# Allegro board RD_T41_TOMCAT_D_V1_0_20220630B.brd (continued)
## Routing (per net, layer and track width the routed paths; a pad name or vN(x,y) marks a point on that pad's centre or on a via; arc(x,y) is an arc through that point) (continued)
DVP_D7: length 16.4
  TOP w0.102: U6.H3 32.65,28.36
  TOP w0.104: v1(23.03,35.33) 23.03,34.8 23.92,33.91 28.04,33.91 28.34,33.6 30.1,33.6 32.3,31.39 32.3,30.28 32.46,30.12 32.46,29.11 32.67,28.9 32.67,28.38 32.65,28.36
  BOTTOM w0.104: v1(23.03,35.33) 23.03,35.46 22.27,36.22 J3.19
DVP_D8: length 14.6
  TOP w0.102: 33,29.46 U6.G1
  TOP w0.104: v1(23.62,35.56) 23.92,35.26 23.92,34.87 24.38,34.42 28.32,34.42 28.6,34.14 30.27,34.14 32.81,31.6 32.81,30.56 32.97,30.4 32.97,29.49 33,29.46
  BOTTOM w0.104: J3.21 23.27,35.91 v1(23.62,35.56)
DVP_D9: length 14.7
  TOP w0.102: 32.97,28.74 U6.G2
  TOP w0.104: v1(23.49,34.92) 23.49,34.9 24.23,34.16 28.22,34.16 28.49,33.88 30.17,33.88 32.56,31.5 32.56,30.38 32.71,30.23 32.71,29.64 32.69,29.62 32.69,29.23 32.97,28.96 32.97,28.74
  BOTTOM w0.104: v1(23.49,34.92) 23.57,34.92 23.77,34.72 J3.22
DVP_D10: length 15.8
  TOP w0.102: U6.G3 33.32,28.38 33.32,29.49 33.22,29.59 33.22,30.51 33.07,30.66 33.07,31.7 30.37,34.39 28.7,34.39 28.67,34.42
  TOP w0.104: v1(24.28,35.64) 24.18,35.53 24.18,34.98 24.48,34.67 28.42,34.67 28.67,34.42
  BOTTOM w0.104: J3.23 24.27,36.23 24.28,36.22 v1(24.28,35.64)
DVP_D11: length 14.7
  TOP w0.102: 30.45,34.65 33.3,31.8 33.3,30.78 33.52,30.56 33.52,28.83 U6.F2
  TOP w0.104: v1(24.56,35.15) 24.76,34.95 28.49,34.95 28.8,34.65 30.45,34.65
  BOTTOM w0.104: J3.24 24.77,34.94 v1(24.56,35.15)
DVP_HSYNC: length 19.9
  TOP w0.102: U6.J2 31.67,28.73 31.67,28.93 31.34,29.26 31.34,30.94 30.37,31.9 v1(29.87,31.9)
  L3_PWR w0.102: v1(16.84,34.7) 17.12,34.42 18.72,34.42 19.38,33.76 28.88,33.76 30.04,32.59 30.04,32.08 v1(29.87,31.9)
  BOTTOM w0.102: J3.8 16.77,34.63 v1(16.84,34.7)
DVP_PCLK: length 14.5
  TOP w0.102: v1(28.29,35.59) 28.29,35.51 28.9,34.9 30.53,34.9 33.55,31.88 33.55,30.89 33.78,30.66 33.78,29.01 33.95,28.84 33.95,28.54 33.65,28.24 U6.F3
  BOTTOM w0.102: v1(28.29,35.59) 28.29,35.38 28.11,35.2 26.78,35.2 25.77,34.19 J3.26
DVP_PWDN: length 12.1
  TOP w0.102: v1(33.12,32.87) 33.14,32.84 33.14,32.61 33.78,31.98 33.78,30.99 34.01,30.76 34.01,29.64 33.98,29.62 33.98,29.21 34.01,29.18 34.01,29.13 34.3,28.85 U6.E2
  L3_PWR w0.102: v1(28.83,35.51) 29.18,35.51 31.59,33.1 32.89,33.1 v1(33.12,32.87)
  BOTTOM w0.102: J3.30 27.77,34.4 28.83,35.46 v1(28.83,35.51)
DVP_RST: length 12.3
  TOP w0.102: U6.E3 34.64,28.4 34.64,29.62 34.87,29.84 34.87,31.67 34.57,31.98 34.57,32.11 34.36,32.31 33.96,32.31 v1(33.63,32.64)
  L3_PWR w0.102: v1(29.76,35.66) 29.76,35.36 31.77,33.35 33.27,33.35 33.68,32.94 33.68,32.69 v1(33.63,32.64)
  BOTTOM w0.102: J3.33 29.27,36.21 29.76,35.71 v1(29.76,35.66)
DVP_VSYNC: length 20.1
  TOP w0.102: v1(30.27,31.5) 30.27,31.47 31.11,30.63 31.11,29.08 31.37,28.83 31.37,28.39 U6.J3
  L3_PWR w0.102: v1(18.56,35) 18.56,34.92 19.5,33.99 28.98,33.99 30.27,32.69 v1(30.27,31.5)
  BOTTOM w0.102: v1(18.56,35) 17.27,36.3 J3.9
EN_DLDO: length 6
  TOP w0.102: U6.U15 26.17,20.26 24.79,18.87 23.49,18.87 22.98,18.36 22.98,17.73 v1(22.68,17.42)
  BOTTOM w0.102: v1(22.68,17.42) 23.1,17.01 R27.2
EXCLKI: length 4.9
  TOP w0.102: C80.2 36.94,32.53 Y1.1 37.05,32.36 37.05,30.82 R23.2 35.6,29.36 U6.C1
EXCLKO: length 2.8
  TOP w0.102: U6.D2 35.25,29.01 35.25,29.49 35.57,29.81 R23.1 R24.2
GMAC_MDCK: length 13.9
  TOP w0.102: U8.22 15.58,20.57 16.43,21.42 16.43,21.87 17.6,23.04 26.23,23.04 26.36,23.16 27.45,23.16 U6.R10
GMAC_MDIO: length 13.7
  TOP w0.102: U6.T10 27.01,23.37 26.26,23.37 26.16,23.27 17.38,23.27 R37.2 15.08,20.96 U8.23
GMAC_PHY_CLK: length 16.5
  TOP w0.102: U8.31 v1(13.25,16.68) ; v1(15.19,23.39) 15.34,23.55 22.82,23.55 R66.1
  L3_PWR w0.102: v1(13.25,16.68) 13.94,17.37 13.94,19.46 15.44,20.95 15.44,23.14 v1(15.19,23.39)
GMAC_RST_N: length 46.5
  TOP w0.102: U8.21 16.08,20.61 16.33,20.86 16.33,20.86 16.98,21.5 C125.1 16.98,21.73 17.9,22.66 v1(18.49,22.66) ; R99.2 23.43,19.6 23.39,19.56 23.31,19.56 22.83,19.08 v1(22.81,19.08) ; U6.A11 38.35,22.86 39.21,22 39.21,19.58 37.31,17.68 36.7,17.68 34.44,15.42 34.44,13.03 32.76,11.35 v1(23.44,11.35)
  TOP w0.203: R70.1 v1(23.44,11.35)
  L3_PWR w0.102: v1(23.44,11.35) 22.12,12.68 22.12,18.44 22.75,19.08 ; 22.75,19.08 v1(22.81,19.08) ; 22.75,19.08 21.41,19.08 20.9,19.58 20.14,19.58 19.07,20.65 19.07,22.38 18.79,22.66 v1(18.49,22.66)
GMAC_RXD0: length 12.6
  TOP w0.102: U6.U13 26.43,21.49 23.06,21.49 22.17,20.6 22.17,18.19 22.3,18.06 22.3,16.81 21.41,15.93 20.29,15.93 20.03,16.18 U8.9
GMAC_RXD1: length 13.5
  TOP w0.102: U8.10 20.15,16.68 R44.2 20.25,16.93 20.57,17.25 21.84,17.25 22.02,17.42 22.02,17.96 21.92,18.06 21.92,20.73 22.98,21.79 26.29,21.79 26.35,21.86 27.24,21.86 27.59,22.21 U6.R12
GMAC_RXDV: length 18.6
  TOP w0.102: U6.U9 26.24,23.9 24.99,23.9 24.53,24.36 22.92,24.36 22.33,23.77 14.02,23.77 13.38,23.14 13.38,20.6 13.05,20.27 13.05,19.56 13.43,19.18 U8.26
GMAC_TXCLK: length 7
  TOP w0.102: R19.1 21.95,22.05 26.23,22.05 26.29,22.1 27.04,22.1 U6.T12
GMAC_TXD0: length 11.1
  TOP w0.102: U6.R11 27.47,22.53 27.04,22.53 27.02,22.51 26.81,22.3 20.27,22.3 19.25,21.29 19.25,19.96 18.97,19.68 U8.16
GMAC_TXD1: length 10.2
  TOP w0.102: U6.T11 26.94,22.86 26.62,22.53 20.04,22.53 18.08,20.57 U8.17
GMAC_TXEN: length 11.1
  TOP w0.102: U6.U11 26.4,22.76 19.94,22.76 18.13,20.95 16.8,20.95 16.58,20.74 U8.20
HPOUTL: length 7.5
  TOP w0.254: U6.T1 26.66,29.84 24.86,29.84 24.63,29.62 22.17,29.62 21.79,30 20.35,30 C107.2
I2C0_SCK: length 24.5
  TOP w0.102: U6.J4 32,27.71 32,29.62 31.8,29.82 31.8,31.22 30.25,32.77 29.51,32.77 29.36,32.61 29.18,32.61 v1(29.13,32.56)
  L3_PWR w0.102: v1(29.13,32.56) 29.08,32.56 28.11,33.53 19.22,33.53 18.59,34.16 16.79,34.16 15.74,35.2 14.75,35.2 v1(14.27,35.69)
  BOTTOM w0.102: J3.3 v1(14.27,35.69)
I2C0_SDA: length 20.4
  TOP w0.102: U6.J1 31.57,29.48 31.57,31.11 30.27,32.41 v1(29.66,32.41)
  L3_PWR w0.102: v1(15.62,34.77) 15.82,34.77 16.71,33.88 18.54,33.88 19.12,33.3 27.76,33.3 28.88,32.18 29.43,32.18 v1(29.66,32.41)
  BOTTOM w0.102: v1(15.62,34.77) 15.77,34.62 J3.6
IR: length 32.2
  TOP w0.102: U6.B12 37,22.21 37.11,22.1 v1(37.49,22.1)
  L3_PWR w0.102: v1(27.76,35.66) 27.76,35.62 28.27,35.1 29.23,35.1 32.86,31.47 39.47,31.47 39.59,31.6 v1(39.7,31.6)
  BOTTOM w0.102: v1(27.76,35.66) 27.61,35.51 26.03,35.51 25.27,36.27 J3.25 ; v1(37.49,22.1) 37.56,22.02 40.41,22.02 41.4,23.01 41.4,30.4 40.15,31.65 39.75,31.65 v1(39.7,31.6)
IRCUTN: length 36.5
  TOP w0.102: v1(38.55,20.98) 38.55,19.61 37.13,18.19 35.06,18.19 U6.E17
  BOTTOM w0.102: v1(38.55,20.98) 38.99,21.41 40.48,21.41 41.93,22.86 41.93,30.91 39.77,33.07 34.39,33.07 34.01,33.45 32.66,33.45 32.37,33.16 29.45,33.16 29.3,33.31 29.3,35.57 29,35.86 28.67,35.86 28.27,36.27 J3.31
IRCUTP: length 33.6
  TOP w0.102: U6.E16 34.3,19.42 35.25,18.47 37.08,18.47 38.02,19.41 v1(38.02,21.54)
  BOTTOM w0.102: v1(38.02,21.54) 38.17,21.69 40.43,21.69 41.65,22.91 41.65,30.86 39.67,32.84 34.29,32.84 33.91,33.22 32.76,33.22 32.46,32.92 29.36,32.92 28.77,33.51 J3.32
LINKA: length 3.2
  TOP w0.102: R75.2 11.58,22.06 11.24,21.72 R76.1 10.47,20.47 J5.8
MCLK: length 1
  TOP w0.102: R67.2 34.3,30.2 U6.E1
MDI_RN: length 1.9
  TOP w0.104: U9.1 20.01,12.19 R40.2
MDI_RP: length 1.6
  TOP w0.104: U9.3 R39.2
MDI_TN: length 4.4
  TOP w0.104: U9.6 13.66,11.4 13.36,11.71 12.87,11.71 12.67,11.91 12.67,12.12 13.67,13.12 R36.2
MDI_TP: length 3.6
  TOP w0.104: U9.8 11.12,11.3 11.5,11.68 12.19,11.68 12.39,11.89 12.39,12.22 12.91,12.74 R13.2
MICBIAS: length 12.7
  TOP w0.254: R81.1 19.9,33.25 20.08,33.07 C110.1 20.94,32.21 v1(21.56,32.21) ; U6.P3 v1(28.12,28.38)
  BOTTOM w0.254: v1(28.12,28.38) 28.01,28.49 28.01,29.26 27.63,29.64 C79.1 C78.1 26.12,31.26 24.91,32.46 21.81,32.46 v1(21.56,32.21)
MICNL: length 11.5
  TOP w0.152: J6.1 13.29,32.81 13.86,32.23 16.09,32.23 C105.1 16.81,31.84 R48.1 20.21,31.84 21.44,30.61 22.69,30.61 C68.2
MICPL: length 10.3
  TOP w0.152: J6.2 14.4,33.5 14.4,32.88 14.69,32.59 16.52,32.59 C105.2 16.81,32.55 R51.2 17.82,32.26 20.29,32.26 21.59,30.96 22.56,30.96 C67.2
MSC0_CLK_PB04: length 6.4
  TOP w0.102: J2.5 28.22,15.14 28.52,15.44 31.47,15.44 32.46,16.43 R25.1
MSC0_CMD_PB05: length 8.3
  TOP w0.102: v1(30.42,12.85) J2.3 30.42,15.08 30.55,15.21 31.67,15.21 33,16.54 U6.G17
  BOTTOM w0.102: v1(30.42,12.85) 30.43,12.86 R30.2
MSC0_D0_PB00: length 12.8
  TOP w0.102: v1(26.02,12.85) J2.7 26.02,15.08 26.72,15.77 31.36,15.77 31.92,16.34 31.92,18.36 32.33,18.77 32.33,19.59 U6.H16
  BOTTOM w0.102: v1(26.02,12.85) 26.1,12.93 R29.2
MSC0_D1_PB01: length 14
  TOP w0.102: U6.J15 32.03,19.93 32.03,18.8 31.7,18.47 31.7,16.43 31.31,16.05 26.36,16.05 24.92,14.61 J2.8 v1(24.92,12.85)
  BOTTOM w0.102: v1(24.92,12.85) 24.85,12.92 R31.2
MSC0_D2_PB02: length 8.5
  TOP w0.102: v1(32.62,12.85) J2.1 32.62,15.4 33.52,16.31 33.52,19.28 33.32,19.48 33.32,19.93 U6.G15
  BOTTOM w0.102: v1(32.62,12.85) 32.61,12.86 R32.2
MSC0_D3_PB03: length 8.1
  TOP w0.102: v1(31.52,12.86) J2.2 31.52,14.65 33.27,16.4 33.27,18.69 33.32,18.75 33.32,19.15 33,19.48 U6.G16
  BOTTOM w0.102: v1(31.52,12.86) 31.52,12.86 R33.2
PHY_LED0: length 21.9
  TOP w0.102: U6.R13 v1(27.48,21.24) ; R74.1 12.8,19.98 12.8,20.37 13.15,20.73 13.15,23.01 13.13,23.04 13.13,23.22 13.92,24 22.24,24 22.82,24.59 24.66,24.59 25.07,24.18 25.55,24.18 v1(25.68,24.31)
  L3_PWR w0.102: v1(27.48,21.24) 27.48,22.73 25.9,24.31 v1(25.68,24.31)
PHY_LED1: length 19.9
  TOP w0.102: U6.R15 v1(27.48,19.94) ; v1(16.15,24.61) 15.95,24.41 12.94,24.41 R75.1
  L3_PWR w0.102: v1(16.15,24.61) 17.12,24.61 17.34,24.38 19.27,24.38 19.86,24.97 22.91,24.97 26.44,21.44 26.44,20.55 27.05,19.94 v1(27.48,19.94)
PHY_RST_N: length 4.1
  TOP w0.102: U6.T13 26.82,21.23 24.93,21.23 C61.2 R99.1
PHYLED0: length 7.7
  TOP w0.102: v1(12.75,23.19) 12.9,23.04 12.9,20.97 R77.2 ; U8.24 14.58,21.38 R88.2 14.37,22.04 14.37,22.96 v1(14.14,23.19)
  BOTTOM w0.102: v1(14.14,23.19) v1(12.75,23.19)
PHYLED1: length 5.2
  TOP w0.102: U8.25 13.44,19.68 13.31,19.81 13.31,20.17 13.92,20.78 v1(13.92,21.18) R89.2 ; R76.2 12.28,21.75 v1(12.49,21.97)
  BOTTOM w0.102: v1(13.92,21.18) 13.13,21.97 v1(12.49,21.97)
PLL_AVDD: length 2.9
  TOP w0.254: U6.D3 v1(35.27,28.38)
  BOTTOM w0.254: FB3.1 35.26,30.73 C30.1 C63.1 35.27,28.98 v1(35.27,28.38)
POR_CTRL: length 2.7
  TOP w0.102: U6.K16 30.81,19.37 30.81,18.45 R78.2 R20.2
PPRST_: length 20
  TOP w0.102: SW2.2 41.09,16.76 40.19,15.86 C111.1 R62.2 37.6,14.73 36.62,14.73 36.01,14.12 v1(36.01,12.88) ; v1(29.66,19.08) 29.87,19.08 U6.L16
  BOTTOM w0.102: v1(36.01,12.88) 35.99,12.9 33.68,12.9 33.14,13.44 33.14,17.32 31.39,19.08 v1(29.66,19.08)
RD_N: length 13
  TOP w0.102: U6.U17 26.88,18.57
  TOP w0.104: 26.88,18.57 26.89,18.56 26.89,17.96 24.91,15.98 23.17,15.98 21.79,14.61 20.6,14.61 19.73,13.74 19.73,13.59 19.81,13.51 19.96,13.51 20.69,14.24 20.88,14.24 21,14.13 21,13.63 R73.1
RD_P: length 13.1
  TOP w0.102: U6.T17 27.15,18.57
  TOP w0.104: 27.15,18.57 27.15,17.85 25.02,15.72 23.27,15.72 21.9,14.35 21.44,14.35 21.26,14.16 21.26,13 20.8,12.55 20.44,12.55 20.04,12.95 19.53,12.95 18.79,12.22 R72.1
RST_OUT: length 3.8
  TOP w0.102: U6.J16 31.21,19.12 v1(31.21,18.69)
  BOTTOM w0.102: v1(31.21,18.69) 31.34,18.69 32.25,17.78 TP8.1
RX+: length 22
  TOP w0.254: v1(8.15,14.58) 8.15,14.57 8.5,14.22 J5.3 ; U9.14 17.47,2.18 17.73,2.44 18.23,2.44 18.49,2.69 v1(18.49,3.15)
  L2_GND w0.254: v1(8.15,14.58) 8.15,9.73 15.01,2.87 18.21,2.87 v1(18.49,3.15)
RX-: length 24.6
  TOP w0.254: U9.16 20.01,2.18 19.76,2.44 19.27,2.44 19.02,2.69 v1(19.02,3.15) ; v1(8.15,15.11) 8.15,15.11 8.5,15.47 J5.4
  L2_GND w0.254: v1(8.15,15.11) 7.93,15.11 7.62,14.8 7.62,9.51 14.79,2.34 18.43,2.34 19.02,2.93 v1(19.02,3.15)
RX_DV: length 3.1
  TOP w0.102: R68.1 28.77,18.33 28.77,20.58 U6.P14
RXD3: length 6.9
  TOP w0.102: v1(22.63,18.31) 22.68,18.36 22.68,18.44 23.34,19.1 24.63,19.1 26.13,20.6 27.49,20.6 U6.R14
  BOTTOM w0.102: R65.1 22.87,18.31 v1(22.63,18.31)
RXDV: length 1.9
  TOP w0.102: v1(18.21,14.78) 18.08,14.91 U8.8
  BOTTOM w0.102: R87.2 18.21,14.59 v1(18.21,14.78)
SD0_CD_N: length 33.1
  TOP w0.102: U6.B11 36.6,22.5 38.38,22.5 38.99,21.89 38.99,19.68 37.23,17.93 36.6,17.93 34.21,15.54 34.21,13.13 32.66,11.58 24.71,11.58 v1(23.82,12.47) J2.9
  BOTTOM w0.102: v1(23.82,12.47) 23.31,12.47 22.93,12.85 R34.2 C92.2 24.2,14.62 Q1.1
SFC_CS_N: length 17.2
  TOP w0.102: U6.T4 26.06,27.41 25.47,26.82 22.55,26.82 21.43,25.7 19.35,25.7 19.02,26.04 18.13,26.04 17.95,26.21 17.45,26.21 17.14,25.91 16.4,25.91 v1(16.05,25.55)
  BOTTOM w0.102: U7.1 14.12,26.49 14.78,25.83 R22.1 15.63,25.13 v1(16.05,25.55)
SFC_SCLK: length 15.8
  TOP w0.102: v1(18.02,24.88) 18.33,24.56 21.93,24.56 22.92,25.55 26.11,25.55 26.34,25.78 27.47,25.78 U6.R6
  BOTTOM w0.102: U7.6 18.79,29.03 18.18,28.42 18.18,25.04 v1(18.02,24.88)
SFC_SIO0: length 15.5
  TOP w0.102: U6.U5 26.44,26.7 26.11,26.7 25.73,26.31 22.71,26.31 21.64,25.25 19.15,25.25 18.82,25.58 17.7,25.58 v1(17.67,25.6)
  BOTTOM w0.102: U7.5 18.79,30.3 17.67,29.18 v1(17.67,25.6)
SFC_SIO1: length 17.9
  TOP w0.102: U6.R5 27.48,26.44 26.77,26.44 26.64,26.31 26.11,26.31 25.85,26.06 22.78,26.06 21.74,25.02 19.05,25.02 18.72,25.35 17.98,25.35 17.8,25.17 16.84,25.17 16.58,25.43 v1(16.58,25.48)
  BOTTOM w0.102: U7.2 12.98,27.76 13.41,27.33 15.34,27.33 16.58,26.09 v1(16.58,25.48)
SFC_SIO2: length 17.8
  TOP w0.102: v1(17.14,25.55) 17.14,25.58 17.55,25.98 17.85,25.98 18.03,25.81 18.92,25.81 19.25,25.48 21.55,25.48 22.64,26.57 25.6,26.57 26.11,27.08 26.82,27.08 U6.T5
  BOTTOM w0.102: U7.3 13.56,29.03 14.09,29.03 17.14,25.98 v1(17.14,25.55)
SFC_SIO3: length 12.9
  TOP w0.102: U6.T6 27.1,26.06 26.23,26.06 25.98,25.81 22.85,25.81 21.83,24.79 18.79,24.79 18.59,24.99 v1(18.56,24.99)
  BOTTOM w0.102: U7.7 18.84,27.76 18.41,27.33 18.41,25.17 18.56,25.02 v1(18.56,24.99)
SPEAK_EN: length 37.9
  TOP w0.102: U6.B10 36.46,23.29 39.21,23.29 40.1,24.18 40.1,25.78 41.37,27.05 41.37,29.16 41.04,29.49 v1(41.04,29.59) ; 16.78,28.01 17.27,28.01 R50.1 ; 16.78,28.01 v1(16.8,28.03) ; 16.78,28.01 U10.1
  L3_PWR w0.102: v1(41.04,29.59) 40.66,29.97 29.84,29.97 28.95,30.86 19.63,30.86 v1(16.8,28.03)
TD_N: length 17.3
  TOP w0.104: R28.1 14.83,12.01 v1(14.73,11.91) ; v1(19,14.5) 19.24,14.5 19.98,15.25 21.59,15.25 22.96,16.62 24.06,16.62 25.84,18.4 25.84,19.11 26.33,19.61 U6.U16
  BOTTOM w0.104: v1(14.73,11.91) 14.53,11.7 14.53,11.43 14.63,11.33 16.35,11.33 18.54,13.51 18.54,13.83 19,14.29 v1(19,14.5)
TD_P: length 18.5
  TOP w0.104: R13.1 v1(14.07,11.94) ; U6.T16 26.82,19.28 26.37,19.28 26.1,19.01 26.1,18.29 24.16,16.36 23.07,16.36 21.7,14.99 20.09,14.99 19.38,14.28 v1(19.38,14.13)
  BOTTOM w0.104: v1(19.38,14.13) 19.2,14.13 18.8,13.72 18.8,13.41 16.46,11.07 14.53,11.07 14.27,11.33 14.27,11.75 v1(14.07,11.94)
TRXN0: length 2
  TOP w0.104: R36.1 16.08,14.76 U8.4
TRXN1: length 3.7
  TOP w0.104: U8.6 17.08,14.98 16.96,14.87 16.96,14.5 17.27,14.2 18.01,14.2 R40.1
TRXP0: length 3.2
  TOP w0.104: R35.1 14.41,13.86 15.03,14.48 15.43,14.48 15.68,14.73 15.68,15.17 15.58,15.28 U8.3
TRXP1: length 3.8
  TOP w0.104: R39.1 17.89,13.25 18.11,13.46 18.11,13.73 17.9,13.94 17.16,13.94 16.7,14.4 16.7,14.86 16.58,14.98 U8.5
TX+: length 18.3
  TOP w0.254: U9.9 11.12,2.21 11.38,2.46 11.85,2.46 12.1,2.72 v1(12.1,3.11) ; v1(6.52,13) 7.84,13 8.23,12.62 8.23,12.1 8.61,11.72 J5.1
  L2_GND w0.254: v1(12.1,3.11) 12.1,3.5 6.52,9.08 v1(6.52,13)
TX-: length 18.6
  TOP w0.254: v1(12.67,3.12) 12.67,2.72 12.92,2.46 13.41,2.46 13.66,2.21 U9.11 ; v1(6.52,13.54) 8.07,13.54 8.59,13.01 8.62,13.01 8.66,12.97 J5.2
  L2_GND w0.254: v1(6.52,13.54) 6.75,13.54 7.06,13.23 7.06,9.3 12.67,3.68 v1(12.67,3.12)
UART1_RX: length 43
  TOP w0.102: v1(30.02,12.19) 30.15,12.32 32.66,12.32 33.19,12.85 33.19,15.62 33.75,16.18 33.75,19.5 U6.F16
  L3_PWR w0.102: v1(14.04,14.86) 13.66,14.86 13.03,14.22 13.03,8.23 16.15,5.11 27.81,5.11 29.97,7.27 29.97,12.15 v1(30.02,12.19)
  BOTTOM w0.102: v1(14.04,14.86) 14.04,14.75 R61.2
UART1_RXD: length 2.9
  BOTTOM w0.102: R57.2 12.25,13.13 R61.1 11.5,14.75 J8.3
UART1_TX: length 44.6
  TOP w0.102: v1(30.83,11.96) 32.64,11.96 33.42,12.75 33.42,15.52 33.98,16.08 33.98,19.92 U6.F15
  L3_PWR w0.102: v1(30.83,11.96) 30.83,10.46 30.22,9.86 30.22,7.16 27.91,4.85 27.73,4.85 27.73,4.86 16.05,4.86 12.78,8.13 12.78,15 13.17,15.39 v1(13.86,15.39)
  BOTTOM w0.102: R60.2 13.48,14.88 13.86,15.27 v1(13.86,15.39)
UART1_TXD: length 2.6
  BOTTOM w0.102: J8.4 12.25,15.75 R58.2 12.26,14.9 R60.1
USB0PN: length 13.8
  TOP w0.13: R100.2 20.52,27.1 15.44,27.1 13.94,25.6 13.32,25.6 v1(13.25,25.68)
  BOTTOM w0.13: v1(13.25,25.68) 13.25,25.63 13.48,25.4 13.48,24.69 12.85,24.05 12.32,24.05 D5.2 11.99,23.74 11.57,24.16 10.82,24.16 10.55,23.89 J4.2
USB0PP: length 13.7
  TOP w0.13: v1(12.87,25.3) 14.07,25.3 15.57,26.8 21.3,26.8 R101.2
  BOTTOM w0.13: J4.3 10.55,24.54 10.62,24.46 11.79,24.46 D3.2 12.33,24.36 12.72,24.36 13.18,24.82 13.18,25.25 13.13,25.3 v1(12.87,25.3)
USB_AVD08: length 3.6
  TOP w0.254: U6.R4 v1(27.47,27.73)
  BOTTOM w0.254: FB4.2 24.36,27.72 C71.1 C72.1 27.46,27.72 v1(27.47,27.73)
USB_AVD18: length 6
  TOP w0.254: U6.T3 27.15,28.06 v1(26.82,28.38)
  BOTTOM w0.254: v1(26.82,28.38) 23.96,28.38 23.44,27.86 C73.1 C36.1 21.69,27.72 FB5.2
USB_AVD33: length 5.8
  TOP w0.203: U6.R3 v1(27.47,28.38)
  BOTTOM w0.254: FB6.2 22.96,28.97 C74.1 C75.1 24.57,28.85 27,28.85 v1(27.47,28.38)
USBID: length 3.1
  TOP w0.102: U6.U2 26.14,28.35 24.58,28.35 TP7.1
N16515966: length 3.1
  BOTTOM w0.305: U2.3 33.17,9.74 R8.2 R6.2 C10.2
N16516036: length 1.2
  BOTTOM w0.254: R4.2 37.17,9.75 U2.4
N16516040: length 2.2
  BOTTOM w0.305: U2.1 35.19,7.84 35.87,7.15 C6.1
N16516370: length 4.9
  BOTTOM w0.203: R1.2 C3.1 20.61,6.64 20.2,7.05 U1.1
N16516568: length 2.9
  BOTTOM w0.305: C4.2 R2.1 R3.2 20.18,4.98 U1.5
N16516732: length 0.9
  BOTTOM w0.254: R14.1 D2.2
N16520392: length 6.3
  TOP w0.406: v1(10.54,23.24) 10.54,23.24 D6.2
  BOTTOM w0.406: J4.1 v1(10.54,23.24) 11.9,21.88 C119.1 11.9,19.98 C95.1 R85.1
N16524050: length 1.9
  TOP w0.254: U10.5 9.61,29.96 J7.2
N16524058: length 2
  TOP w0.254: U10.8 10.37,28.01 9.89,28.48 J7.1
N16524110: length 1.6
  TOP w0.254: R53.1 16.89,29.79 16.72,29.96 U10.4
N16524120: length 0.7
  TOP w0.254: R53.2 C107.1
N16524124: length 0.7
  TOP w0.254: R52.2 C106.1
N16524196: length 1.7
  TOP w0.254: R52.1 16.99,28.93 16.61,29.31 U10.3
N16524342: length 2.5
  TOP w0.254: R51.1 18.08,33.59 R81.2 18.41,33.24 v1(18.41,32.74)
  BOTTOM w0.254: C56.2 18.41,32.2 v1(18.41,32.74)
N16524476: length 3
  TOP w0.254: R49.2 17.86,31.14 R48.2 17.15,31.17 v1(17.05,31.17)
  BOTTOM w0.254: v1(17.05,31.17) C56.1
N16557488: length 4.9
  TOP w0.102: C82.2 34.92,33.91 Y1.3 36.15,33.56 36.15,31.99 36.61,31.53 R24.1
N16609473: length 1.1
  TOP w0.254: v1(33.96,20.93) 33.96,21.24 U6.F13
  BOTTOM w0.254: R16.1 v1(33.96,20.93)
N16609477: length 3
  TOP w0.102: U6.D9 35.28,23.83 37.3,23.83 37.38,23.9 R18.1
N16629326: length 1.8
  TOP w0.102: U8.28 13.26,18.18 12.87,18.57 R46.2
N16629374: length 2.5
  TOP w0.102: R47.2 12.54,14.91 12.72,15.09 12.72,15.62 13.28,16.18 U8.32
N16629796: length 3.3
  TOP w0.102: U8.1 14.58,14.76 14.22,14.4 13.38,14.4 13.03,14.05 R41.1
N16629982: length 2.6
  TOP w0.254: C103.1 C104.1 12.3,17.68 U8.29
N16630018: length 2.5
  TOP w0.254: U8.2 v1(15.08,14.94)
  BOTTOM w0.254: C101.1 15.58,13.26 C102.1 15.58,14.44 v1(15.08,14.94)
N16630046: length 2.7
  TOP w0.102: U8.30 13.09,17.18 12.82,16.92 12.82,16.08 12.52,15.77 R94.1
N16630124: length 1.1
  TOP w0.406: U9.7 v1(12.01,10.59)
  BOTTOM w0.406: v1(12.01,10.59) 11.26,10.59 C98.2
N16630144: length 1.2
  TOP w0.508: v1(18.33,1.4) 18.34,1.39 U9.15 ; U9.10 11.99,1.39 v1(11.98,1.4) ; v1(15.77,1.4) 15.77,1.39 U9.13
N16630182: length 1.7
  TOP w0.406: v1(14.93,9.53) U9.5
  BOTTOM w0.406: C97.2 v1(14.93,9.53)
N16630194: length 3.7
  TOP w0.406: v1(16.96,8.79) 17.85,8.79 18.74,9.68 U9.2
  BOTTOM w0.406: C96.2 16.82,8.8 16.84,8.79 v1(16.96,8.79)
N16630328: length 3.5
  BOTTOM w0.508: R93.1 8.84,5.1 C126.2
N16679971: length 3
  TOP w0.102: R21.2 37.68,27.74 35.28,27.74 U6.D4
N16680187: length 9.3
  TOP w0.254: v1(27.13,30.03) U6.R1
  BOTTOM w0.254: FB7.2 21.89,30.24 21.89,31.02 22.13,31.27 22.22,31.27 22.45,31.5 22.45,31.58 C66.1 23.52,31.89 23.59,31.81 C65.1 24.27,31.81 24.38,31.93 24.79,31.93 25.95,30.76 26.82,30.76 27.13,30.45 v1(27.13,30.03)
N16680357: length 2.5
  TOP w0.254: U6.R2 v1(27.47,29.03)
  BOTTOM w0.254: C69.1 C70.1 27.14,29.36 v1(27.47,29.03)
N16685513: length 3.2
  TOP w0.102: U6.T9 26.66,23.67 24.44,23.67 R66.2
N16707574: length 6
  TOP w0.13: U6.T2 26.82,29.03 25.78,29.03 25.45,28.7 23.03,28.7 22.06,27.73 R101.1
N16707578: length 5.6
  TOP w0.13: R100.1 21.96,28.06 22.91,29.01 25.32,29.01 25.65,29.34 26.38,29.34 26.39,29.36 U6.U1
N16707590: length 5.9
  TOP w0.102: 27.96,29.74 28.11,29.59 28.11,29.18 28.45,28.85 U6.P2
  TOP w0.152: C68.1 23.91,30.53 24.11,30.73 26.97,30.73 27.96,29.74
N16707598: length 0.4
  TOP w0.102: U6.P15 v1(28.13,19.94)
N16710875: length 2.4
  TOP w0.102: U6.H15 32.66,19.94 32.66,18.64 32.46,18.44 R25.2
N16712105: length 7.1
  TOP w0.102: 28.34,29.74 28.34,29.24 28.77,28.81 28.77,28.38 U6.N3
  TOP w0.152: 28.34,29.74 28.34,29.87 28.22,29.99 28.21,29.99 27.12,31.09 24.15,31.09 24.06,31.18 24.04,31.18 23.96,31.27 C67.1
N16792128: length 3.4
  TOP w0.102: U6.T15 27.03,20.26 26.7,19.92 26.32,19.92 24.72,18.33 R26.1
N16932770: length 4.9
  BOTTOM w0.203: R11.2 C62.1 26.91,6.64 26.55,7 U4.1
N16932830: length 2.9
  BOTTOM w0.305: U4.5 26.53,4.98 R98.2 R86.1 C16.2
N16959210: length 5
  BOTTOM w0.254: U3.1 36.49,16.06 36.95,15.6 39.01,15.6 39.28,15.86 C14.1 R5.2
N16959271: length 2.9
  BOTTOM w0.305: C9.2 R7.1 R9.2 36.44,13.97 U3.5
N16959996: length 5.1
  BOTTOM w0.203: R10.2 19.39,18.3 18.98,18.71 C112.1 18.98,21.29 19.68,21.98 U5.1
N16967238: length 2.2
  TOP w0.102: R19.2 19.69,19.85 19.03,19.18 U8.15

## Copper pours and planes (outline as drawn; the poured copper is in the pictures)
GND on TOP: 35.91,19.76 36.6,20.45 36.6,27.91 35.81,28.7 28.32,28.7 27.17,27.56 27.17,20.32 27.73,19.76
GND on TOP: 6,0.41 5.58,0.58 5.41,1 5.41,37 5.58,37.42 6,37.59 42,37.59 42.42,37.42 42.59,37 42.59,1 42.42,0.58 42,0.41 ; 7 cut-outs
GND on BOTTOM: 6,0.41 5.58,0.58 5.41,1 5.41,37 5.58,37.42 6,37.59 42,37.59 42.42,37.42 42.59,37 42.59,1 42.42,0.58 42,0.41 ; 5 cut-outs
GND on L2_GND, L3_PWR: 6,0.41 5.58,0.58 5.41,1 5.41,37 5.58,37.42 6,37.59 42,37.59 42.42,37.42 42.59,37 42.59,1 42.42,0.58 42,0.41
VCC_0V8 on TOP: 31.44,20.98 32.18,20.98 32.81,21.62 32.81,27.23 32.71,27.33 29.49,27.33 28.09,25.93 28.09,23.7 28.49,23.29 29.16,23.29 29.31,23.44 29.31,24.1 29.28,24.13 29.28,25.43 30.27,26.42 31.82,26.42 32,26.24 32,22.23 31.72,21.95 30.96,21.95 30.45,21.44 29.89,21.44 29.59,21.13 29.59,20.7 29.71,20.57 31.03,20.57
VCC_0V8 on BOTTOM: 31.62,21.77 31.97,22.12 31.97,26.72 31.82,26.87 30.35,26.87 30.17,26.7 30.17,26.42 29.37,25.62 29.37,23.03 29.18,22.83 28.55,22.83 28.47,22.91 28.47,24.05 27.73,24.79 24.28,24.79 24.13,24.64 24.1,24.47 24.1,22.17 24.05,22.12 22.07,22.12 22.04,22.15 22.04,25.35 23.01,26.31 26.95,26.31 27.3,26.67 28.85,26.67 29.1,26.92 29.1,27.3 29.31,27.51 29.31,27.87 29.47,28.02 32.46,28.02 32.89,27.59 32.89,21.16 32.37,20.64 31.73,20.64 31.57,20.47 29.16,20.47 29.13,20.5 29.13,21.21 29.38,21.46 30.65,21.46 30.96,21.77
VCC_0V8 on L3_PWR: 33.14,22.68 32.28,22.68 32.03,22.94 32.03,26.09 31.57,26.54 30.1,26.54 29.31,25.76 29.31,23.62 28.29,23.62 28.27,23.65 28.27,26.49 29.38,27.61 32.69,27.61 33.14,27.15
VCC_1V8 on BOTTOM: 27.17,11.33 27.07,11.43 24.99,11.43 24.68,11.13 24.68,9.58 24.81,9.45 27.12,9.45 27.17,9.5
VCC_1V8 on L3_PWR: 24.71,9.83 26.06,9.83 26.37,10.15 26.37,11.37 29.43,14.43 30.67,15.66 30.67,16.53 30.51,16.69 29.43,16.69 24.53,11.79 24.53,10.01
VCC_3V3 on BOTTOM: 17.95,9.45 17.89,9.51 17.89,11.11 18.28,11.51 18.28,11.96 20.34,14.02 20.34,16.76 20.52,16.94 21.59,16.94 21.66,16.87 21.66,13.84 19.63,11.81 19.63,11.43 19.73,11.33 20.77,11.33 20.82,11.28 20.82,9.55 20.72,9.45
VCC_3V3 on L3_PWR: 21.21,17.17 21.21,16.81 21.38,16.64 21.38,16.15 21.31,16.08 18.61,16.08 18.11,16.59 18.11,19.08 16,21.18 16,23.24 14.17,25.07 14.17,25.88 11.65,28.4 11.65,34.39 13.05,35.79 13.38,35.79 13.67,35.5 13.67,34.2 12.62,33.15 12.62,28.88 15.31,26.19 15.31,25.35 16.94,23.72 16.94,21.54 19.2,19.28 19.2,17.93 19.78,17.35 21.03,17.35
VCC_3V3 on L3_PWR: 26.95,16.05 27.86,16.05 28.93,17.12 32.18,17.12 38.65,23.6 38.65,25.45 39.58,26.38 39.06,26.9 38.58,26.9 37.61,25.93 37.61,24.03 31.67,18.08 27.96,18.08 26.82,16.94 26.82,16.18
VCC_5V on BOTTOM: 30.04,37.13 30.04,35.97 30.2,35.81 30.2,35.41 29.54,34.75 29.54,33.5 29.64,33.4 31.01,33.4 31.01,36.83 30.7,37.13
VCC_5V on BOTTOM: 21.54,5.66 21.66,5.79 22.53,5.79 22.83,5.49 22.83,5.18 22.93,5.08 23.52,5.08 23.54,5.05 23.54,2.59 23.69,2.44 27.56,2.44 27.89,2.77 27.89,5.71 27.96,5.79 28.93,5.79 29.23,5.49 29.23,5.21 29.33,5.11 30.02,5.11 30.15,5.23 30.15,10.62 32.04,12.51 37.14,12.51 37.69,13.06 37.69,14.68 37.82,14.81 38.81,14.81 39.32,14.3 39.85,14.3 40.1,14.05 40.1,12.6 38.91,11.4 32.58,11.4 31.21,10.03 31.21,5.38 31.38,5.22 31.78,5.22 32.41,5.84 34.36,5.84 34.51,5.99 35.56,5.99 35.58,5.97 35.58,3.99 35.53,3.94 34.13,3.94 34.03,4.04 33.07,4.04 32.66,3.63 32.66,1.98 31.7,1.02 21.79,1.02 21.54,1.27
VCC_5V on BOTTOM: 8.76,17.45 7.97,18.24 6.35,18.24 6.07,18.52 6.07,19.58 6.47,19.99 8.63,19.99 9.39,19.23 13.53,19.23 13.76,19.46 13.76,20.35 14.3,20.88 17.85,20.88 18.03,20.7 18.03,19.76 17.95,19.68 16.07,19.68 15.77,19.38 15.77,17.7 15.52,17.45
VCC_5V on L3_PWR: 6.37,19.94 8.71,19.94 8.95,19.7 8.95,10.78 16.02,3.71 23.26,3.71 23.75,3.23 23.75,1.37 23.36,0.99 13.23,0.99 6.07,8.15 6.07,19.63
VCC_12V on TOP: 38.07,8.41 42.16,8.41 42.41,8.15 42.41,6.73 42.24,6.55 38.45,6.55 38.05,6.96 38.05,8.38
VCC_12V on BOTTOM: 38.2,8.36 38.68,7.87 38.68,7.24 39.34,6.58 42.19,6.58 42.41,6.81 42.41,9.32 42.29,9.45 37.97,9.45 37.74,9.22 36.7,9.22 36.65,9.17 36.65,8.41 36.7,8.36
VCC_DDR on TOP: 33.52,27.08 33.52,22 33.88,21.64 34.74,21.64 34.87,21.77 34.87,25.88 34.08,26.67 34.08,26.87 34.18,26.97 34.18,27.25 34.11,27.33 33.78,27.33
VCC_DDR on BOTTOM: 34.72,18.36 34.36,18.72 34.36,21.34 34.11,21.59 33.91,21.59 33.78,21.72 33.78,27.28 33.83,27.33 34.24,27.33 34.29,27.28 34.29,26.92 34.46,26.75 35.28,26.75 35.58,26.44 35.58,22.78 35.96,22.4 35.96,21.54 36.09,21.41 36.09,20.57 36.24,20.42 37,20.42 37.16,20.27 37.16,18.52 37,18.36
N16516056 on BOTTOM: 36.65,8.03 36.65,6.4 36.92,6.13 36.92,3.95 37.03,3.84 38.48,3.84 38.73,4.09 38.73,6.53 38.22,7.04 38.22,7.72 37.89,8.05 36.67,8.05
N16516600 on BOTTOM: 21.81,7.24 22.7,7.24 22.81,7.34 22.81,8.46 23.31,8.97 23.31,11.18 23.06,11.43 21.81,11.43 21.74,11.35 21.74,8.94 21.79,8.89 21.79,7.26
N16630144 on BOTTOM: 10.33,2.06 13.28,2.06 13.53,2.31 13.53,2.95 15.49,4.9 15.64,4.9 17.22,3.33 17.22,2.44 17.75,1.91 18.49,1.91 18.89,1.5 18.89,1.17 18.74,1.02 10.41,1.02 10.18,1.24 10.18,1.91
N16932828 on BOTTOM: 28.14,7.26 28.16,7.24 29.05,7.24 29.16,7.34 29.16,8.41 29.59,8.84 29.59,11.3 29.46,11.43 28.16,11.43 28.09,11.35 28.09,8.86 28.14,8.81
N16959277 on BOTTOM: 38.1,16.26 38.93,16.26 39.09,16.41 39.09,17.45 39.67,18.03 39.67,20.14 39.42,20.4 38.15,20.4 38.07,20.32 38.07,16.28
N16960077 on BOTTOM: 19.48,20.37 19.48,19.66 19.71,19.43 23.9,19.43 24.1,19.63 24.1,20.65 24.05,20.7 21.41,20.7 21.13,20.42 19.53,20.42

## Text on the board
BOTTOM: ArtWork BOTTOM
Package Geometry/Pastemask Bottom: ArtWork Pastebot
Ref Des/Silkscreen Bottom: ADC0 | RST_OUT | USB | DEBUG | 3V3 | 0V8 | 1V8 | 5V | VCCDDR | 12V | DVP_CON | ArtWork Silkbot
User.Comments: ArtWork Soldertop | ArtWork Solderbot
TOP: ArtWork TOP
Package Geometry/Pastemask Top: ArtWork Pastetop
Ref Des/Silkscreen Top: ETH | R- | R+ | T- | T+ | SPK | MIC | USBID | SDCARD | VBUS | BOOTSEL0 | GND | 12V | NC | PPRST_ | ArtWork Silktop
L2_GND: ArtWork L2_GND
L3_PWR: ArtWork L3_PWR
DIMENSION: 1,4 | 4X
NCLEGEND-1-4: FIGURE | SIZE | 8.0 | 23.622 | 39.37 | 47.244x19.685 | 118.11x78.74 | DRILL CHART: TOP to BOTTOM | ALL UNITS ARE IN MILS | PLATED | NON-PLATED | QTY | 497 | 2
